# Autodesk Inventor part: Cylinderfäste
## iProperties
Created: 2001-12
Part Number: Cylinderfäste
Material: SS2132
Document SubType Name: Modeling
Designer: Tobben
Control State: 0
Master: False
Checked Out: False
Shininess: 64.0
Length Units: 11269
Angle Units: 11279
Time Units: 11290
Mass Units: 11283
Length Display Precision: 3
Angle Display Precision: 2
Compacted: True
Density: 0.0
Volumn: 0.0
Area: 0.0
PropertySet Name: Model Information
Author: Tobben
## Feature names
1. Extrusion1
2. Extrusion2
3. Extrusion3
4. Fillet1
